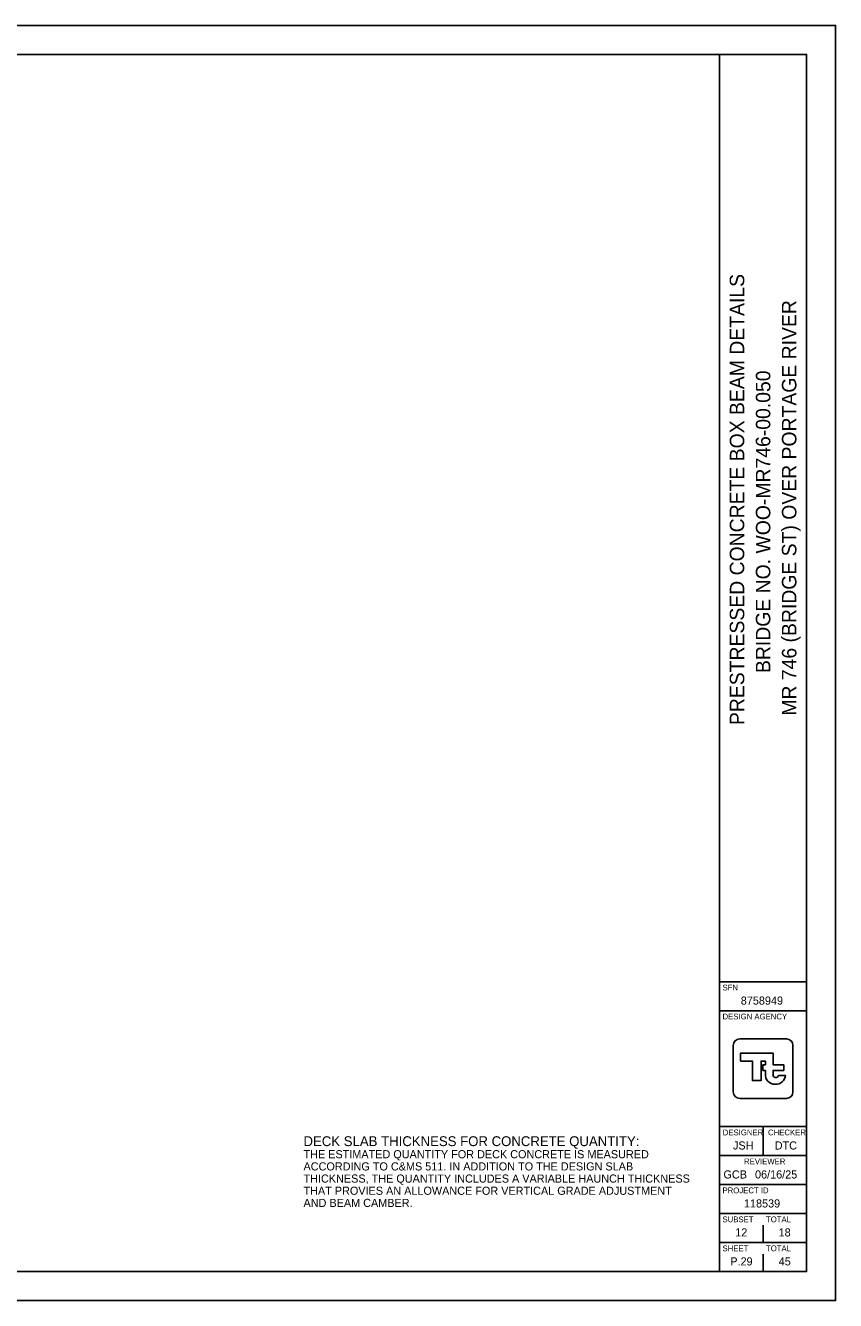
# Model space of a CAD drawing. Extents: x -5.1 to 34, y -2.1 to 22.
# Drawn here: x 20.02 to 34, y 0 to 22 of the extents above; entities that cross this region are included whole.
import ezdxf

# ---------------------------------------------------------------- set-up
doc = ezdxf.new("R2010")
doc.units = 0
for name, color, linetype in [('BR_P_Gen_Text', 7, 'Continuous'), ('SH_Border', 7, 'Continuous'), ('SH_Cut_Line', 7, 'Continuous'), ('SH_Data', 7, 'Continuous')]:
    doc.layers.add(name, color=color, linetype=linetype)

msp = doc.modelspace()

# ---------------------------------------------------------------- linework, layer by layer
at = {"layer": 'SH_Border'}
for p, q in [((32, 0.5), (32, 21.5)), ((32, 5.5), (33.5, 5.5)), ((32, 5), (33.5, 5)), ((32, 3), (33.5, 3)), ((32.75, 3), (32.75, 2.5)), ((32, 2.5), (33.5, 2.5)), ((32, 2), (33.5, 2)), ((32, 1.5), (33.5, 1.5)), ((32, 1), (33.5, 1))]:
    msp.add_line(p, q, dxfattribs=at)
msp.add_lwpolyline([(1.5, 21.5), (33.5, 21.5), (33.5, 0.5), (1.5, 0.5)], close=True, dxfattribs=at)
at = {"layer": 'SH_Cut_Line'}
msp.add_lwpolyline([(0, 0), (34, 0), (34, 22), (0, 22)], close=True, dxfattribs=at)
at = {"layer": 'SH_Data'}
for p, q in [((32.75, 4), (32.75, 4)), ((32.791, 3.915), (32.791, 3.915)), ((33.136, 3.885), (33.015, 3.885)), ((32.75, 1), (32.75, 1.3)), ((32.375, 0.675), (32.375, 0.675)), ((32.75, 0.5), (32.75, 0.8))]:
    msp.add_line(p, q, dxfattribs=at)
for points in [[(32.236, 3.599), (32.236, 4.401)], [(32.348, 4.514), (33.152, 4.514)], [(33.264, 4.401), (33.264, 3.599)], [(32.922, 3.899), (32.922, 3.97), (33.107, 3.97), (33.107, 4.068), (32.922, 4.068), (32.922, 4.268), (32.361, 4.268), (32.361, 4.132), (32.566, 4.132), (32.566, 3.794), (32.715, 3.794), (32.715, 4.13), (32.79, 4.13), (32.79, 4.068), (32.748, 4.068), (32.748, 3.97), (32.79, 3.97), (32.79, 3.915), (32.791, 3.915)], [(33.152, 3.486), (32.348, 3.486)]]:
    msp.add_lwpolyline(points, dxfattribs=at)
for centre, radius, start, end in [((32.348, 4.401), 0.113, 90, 180), ((33.152, 4.401), 0.113, 360, 90), ((32.949, 3.892), 0.16, 171.8856, 274.8323), ((32.968, 3.892), 0.0473, 171.8856, 350.9243), ((32.976, 3.892), 0.16, 265.1677, 357.3201), ((32.348, 3.599), 0.113, 180, 270), ((33.152, 3.599), 0.113, 270, 360)]:
    msp.add_arc(centre, radius, start, end, dxfattribs=at)

# ---------------------------------------------------------------- texts
at = {"layer": 'BR_P_Gen_Text'}
for s, height, p in [('DECK SLAB THICKNESS FOR CONCRETE QUANTITY:', 0.17, (24.818, 2.664)), ('THE ESTIMATED QUANTITY FOR DECK CONCRETE IS MEASURED ', 0.14, (24.818, 2.454)), ('ACCORDING TO C&MS 511. IN ADDITION TO THE DESIGN SLAB ', 0.14, (24.818, 2.244)), ('THICKNESS, THE QUANTITY INCLUDES A VARIABLE HAUNCH THICKNESS ', 0.14, (24.818, 2.034)), ('THAT PROVIES AN ALLOWANCE FOR VERTICAL GRADE ADJUSTMENT ', 0.14, (24.818, 1.824)), ('AND BEAM CAMBER.', 0.14, (24.818, 1.614))]:
    msp.add_text(s, height=height, dxfattribs=at).set_placement(p)
at = {"layer": 'SH_Data'}
for s, p in [('PRESTRESSED CONCRETE BOX BEAM DETAILS', (32.425, 9.929)), ('MR 746 (BRIDGE ST) OVER PORTAGE RIVER', (33.325, 10.091)), ('BRIDGE NO. WOO-MR746-00.050', (32.875, 10.827))]:
    msp.add_text(s, height=0.25, rotation=90, dxfattribs=at).set_placement(p)
for s, height, p in [('SFN', 0.1, (32.05, 5.35)), ('8758949', 0.14, (32.365, 5.105)), ('DESIGN AGENCY', 0.1, (32.05, 4.85)), ('DESIGNER', 0.1, (32.054, 2.85)), ('CHECKER', 0.1, (32.835, 2.85)), ('JSH', 0.14, (32.23, 2.605)), ('DTC', 0.14, (32.951, 2.605)), ('REVIEWER', 0.1, (32.422, 2.35)), ('GCB', 0.14, (32.066, 2.105)), ('06/16/25', 0.14, (32.611, 2.105)), ('PROJECT ID', 0.1, (32.05, 1.85)), ('118539', 0.14, (32.42, 1.605)), ('SUBSET', 0.1, (32.05, 1.35)), ('TOTAL', 0.1, (32.8, 1.35)), ('12', 0.14, (32.269, 1.105)), ('18', 0.14, (33.018, 1.105)), ('SHEET', 0.1, (32.05, 0.85)), ('TOTAL', 0.1, (32.8, 0.85)), ('P.29', 0.14, (32.184, 0.605)), ('45', 0.14, (33.02, 0.605))]:
    msp.add_text(s, height=height, dxfattribs=at).set_placement(p)

doc.saveas('drawing.dxf')
